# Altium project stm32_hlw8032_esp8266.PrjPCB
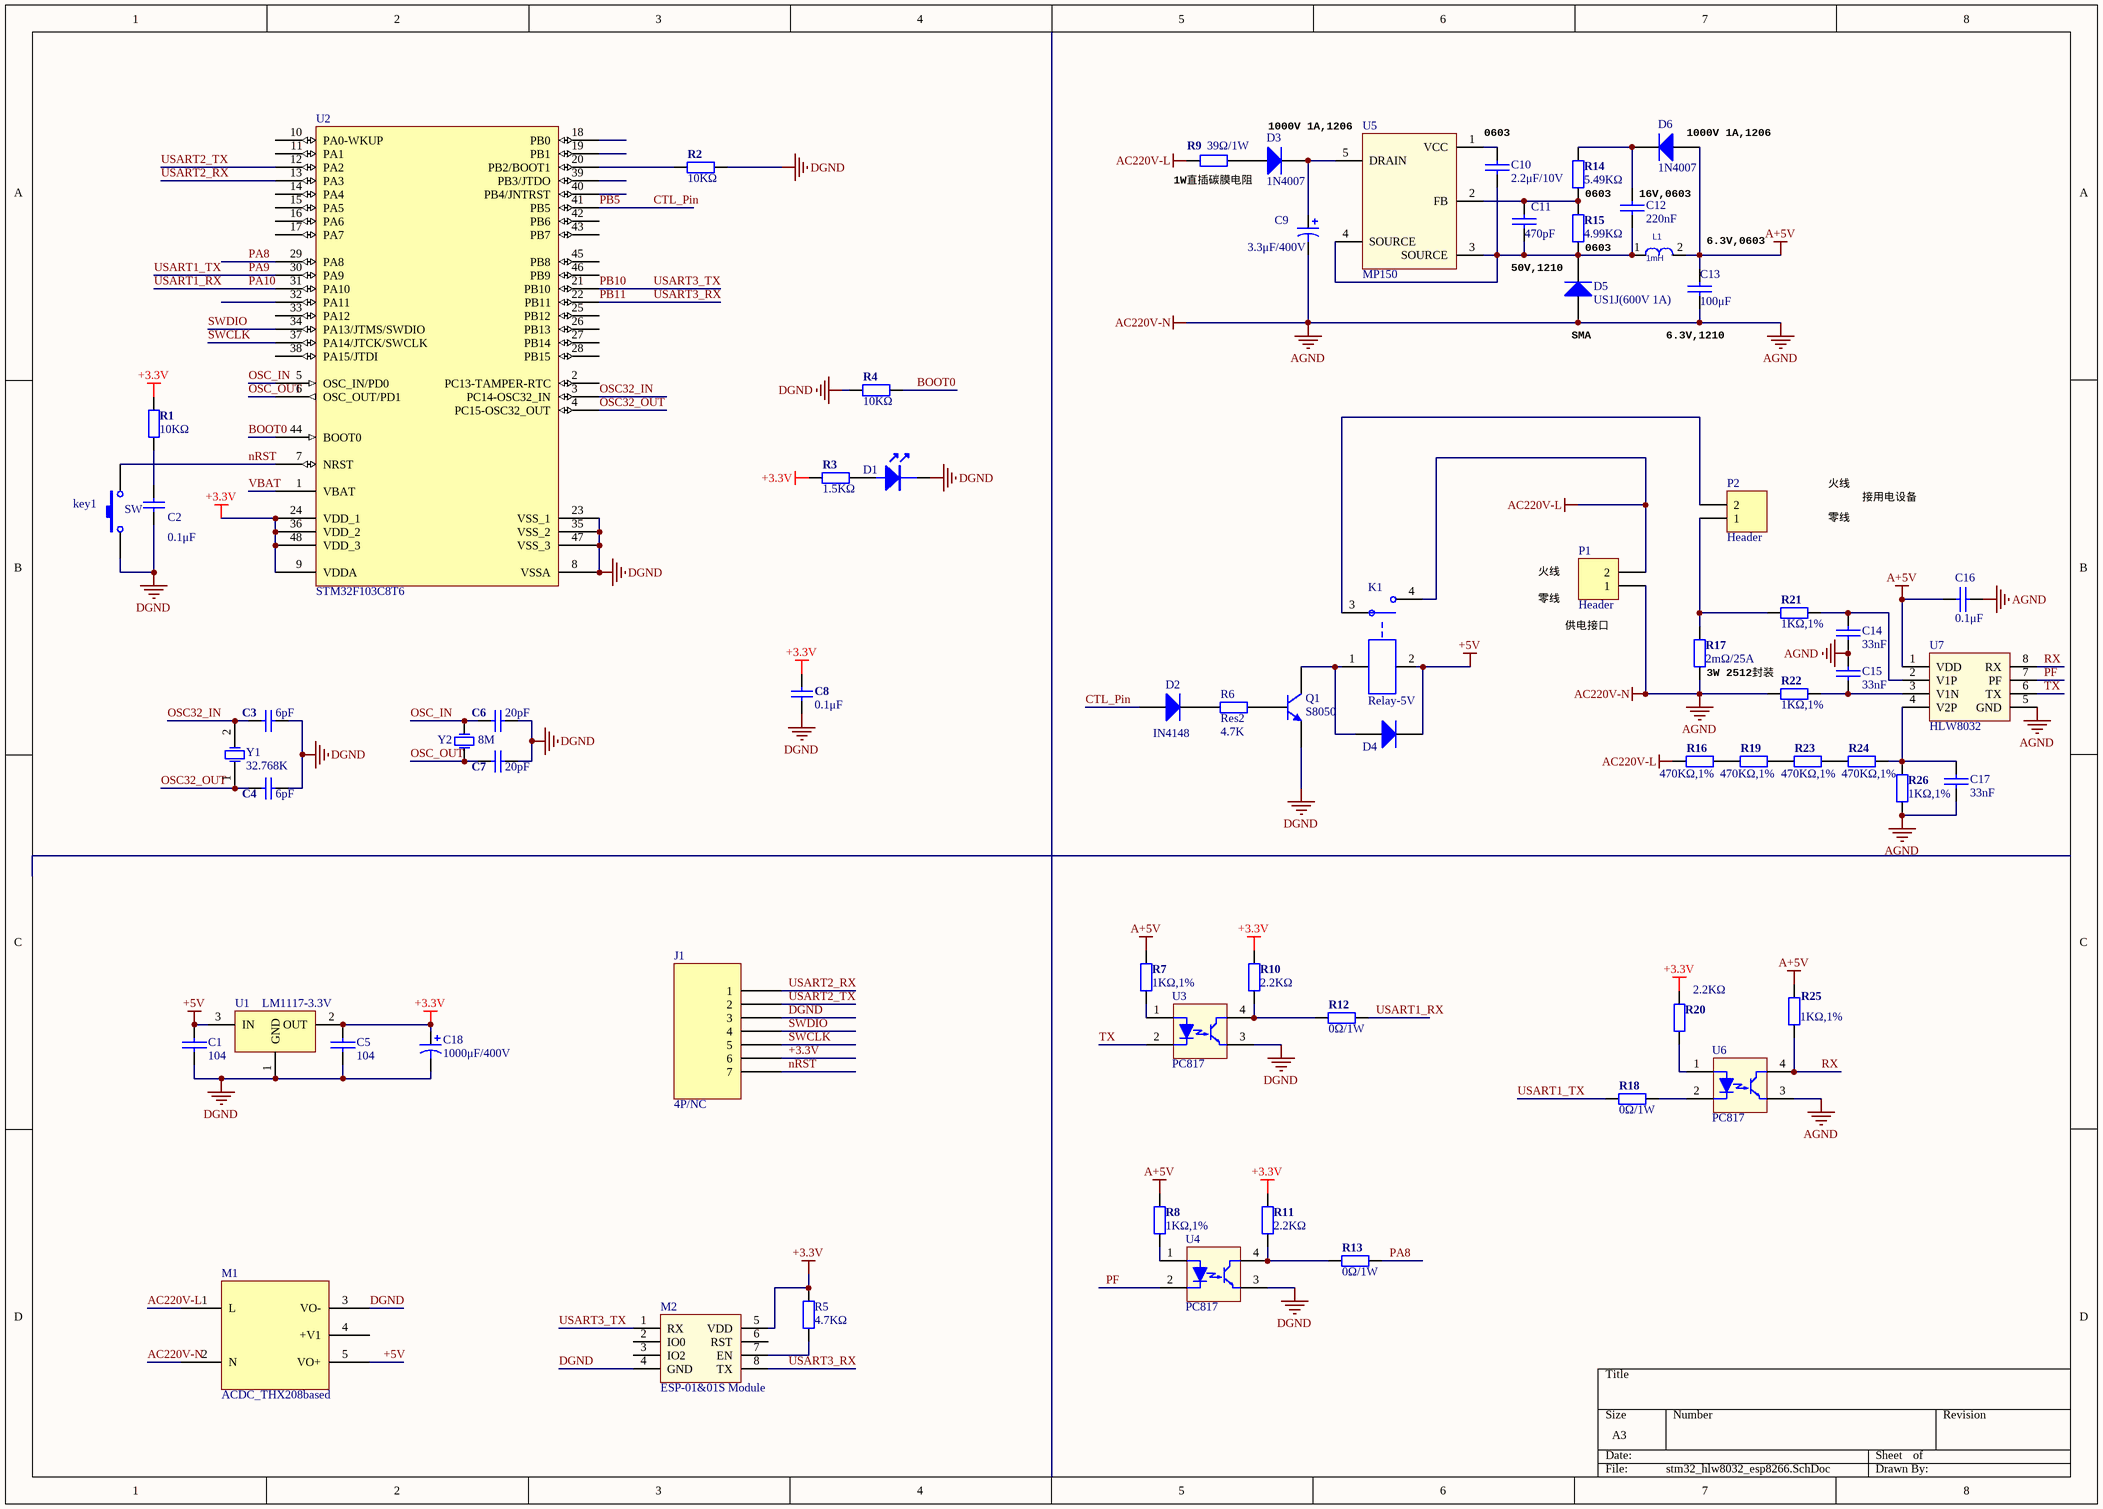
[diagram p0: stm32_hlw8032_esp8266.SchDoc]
1 sheet, 68 parts. Net scope: global (net labels, ports and power ports of the same name join across sheets).
Board file: stm32_hlw8032_esp8266.PcbDoc

## Sheet stm32_hlw8032_esp8266.SchDoc: Smartplug
size A3

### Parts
C1  104  [0603C]
C2  0.1μF  [LC-0603_C]
C3  6pF  [LC-0603_C]
C4  6pF  [LC-0603_C]
C5  104  [0603C]
C6  20pF  [LC-0603_C]
C7  20pF  [LC-0603_C]
C8  0.1μF  [LC-0603_C]
C9  3.3μF/400V  [CAP-ELECT-TH-6.3X7]
C10  2.2μF/10V  [LC-0603_C]
C11  470pF  [LC-0603_C]
C12  220nF  [LC-0603_C]
C13  100μF  [LC-1210_C]
C14  33nF  [LC-0805_C]
C15  33nF  [LC-0805_C]
C16  0.1μF  [LC-0603_C]
C17  33nF  [LC-0805_C]
C18  1000μF/400V  [CAP-ELECT-TH-6.3X7]
D1  POWER  [LC-0603_LED_S1]  (value not drawn)
D2  IN4148  [1206D]
D3  1N4007  [LC-SMA(DO-214AC)_S1]
D4  (no value)  [1206D]
D5  US1J(600V 1A)  [LC-SMA(DO-214AC)_S1]
D6  1N4007  [LC-SMA(DO-214AC)_S1]
J1  4P/NC  [HDR1X7]
K1  Relay-5V  [SJ-S-105LMH]
key1  SW  [KEY-2]
L1  1mH  [L-10X14]
M1  ACDC_THX208based  [ACDC_THX208]
M2  ESP-01&01S Module  [ESP-01&01S Module]
P1  Header  [3.81-2P]
P2  Header  [3.81-2P]
Q1  S8050  [SOT-23]
R1  10KΩ  [LC-0603_R]
R2  10KΩ  [LC-0603_R]
R3  1.5KΩ  [LC-0603_R]
R4  10KΩ  [LC-0603_R]
R5  4.7KΩ  [LC-0603_R]
R6  Res2  value 4.7K  [0603]
R7  1KΩ,1%  [LC-0805_R]
R8  1KΩ,1%  [LC-0805_R]
R9  39Ω/1W  [R-1W-THT]
R10  2.2KΩ  [LC-0603_R]
R11  2.2KΩ  [LC-0603_R]
R12  0Ω/1W  [0603]
R13  0Ω/1W  [0603]
R14  5.49KΩ  [LC-0603_R]
R15  4.99KΩ  [LC-0603_R]
R16  470KΩ,1%  [LC-0805_R]
R17  2mΩ/25A  [R2512]
R18  0Ω/1W  [0603]
R19  470KΩ,1%  [LC-0805_R]
R20  2.2KΩ  [LC-0603_R]
R21  1KΩ,1%  [LC-0805_R]
R22  1KΩ,1%  [LC-0805_R]
R23  470KΩ,1%  [LC-0805_R]
R24  470KΩ,1%  [LC-0805_R]
R25  1KΩ,1%  [LC-0805_R]
R26  1KΩ,1%  [LC-0805_R]
U1  LM1117-3.3V  [SOT-223/P2.3]
U2  STM32F103C8T6  [LC-LQFP-48_7x7x05P]
U3  PC817  [LC-SMD-4]
U4  PC817  [LC-SMD-4]
U5  MP150  [LC-SOT-23-5]
U6  PC817  [LC-SMD-4]
U7  HLW8032  [LC-SOP-8_150mil]
Y1  32.768K  [CRYSTAL]
Y2  8M  [49/U_N]

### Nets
+3.3V: C5.1 C8.2 C18.1 J1.6 M2.5(VDD) R1.2 R3.2 R5.2 R10.2 R11.2 R20.2 U1.2(OUT) U2.9(VDDA) U2.24(VDD_1) U2.36(VDD_2) U2.48(VDD_3)
+5V: C1.1 D4.2(K) K1.2 M1.5(VO+) U1.3(IN)
A+5V: C13.2 C16.1 D6.1(A) L1.2 R7.2 R8.2 R25.2 U7.1(VDD)
AC220V-L: K1.4 M1.1(L) P1.2 R9.1 R16.2
AC220V-N: C9.2 C13.1 C14.2 C15.1 C16.2 C17.2 D5.1(A) M1.2(N) P1.1 R17.2 R22.2 R26.2 U6.3(A2) U7.5(GND)  [also labelled AGND]
DGND: C1.2 C2.1 C3.2 C4.2 C5.2 C6.2 C7.2 C8.1 C18.2 D1.K J1.3 key1.1 M1.3(VO-) M2.4(GND) Q1.2(E) R2.1 R4.2 U1.1(GND) U2.8(VSSA) U2.23(VSS_1) U2.35(VSS_2) U2.47(VSS_3) U3.3(A2) U4.3(A2)
BOOT0: R4.1 U2.44(BOOT0)
CTL_Pin: D2.1(A) U2.41(PB5)  [also labelled PB5]
nRST: J1.7 key1.2 U2.7(NRST)
OSC32_IN: C3.1 U2.3(PC14-OSC32_IN) Y1.2(OSC2)
OSC32_OUT: C4.1 U2.4(PC15-OSC32_OUT) Y1.1(OSC1)
OSC_IN: C6.1 U2.5(OSC_IN/PD0) Y2.1
OSC_OUT: C7.1 U2.6(OSC_OUT/PD1) Y2.2
PA8: R13.2 U2.29(PA8)
PA9: R18.1 U2.30(PA9)  [also labelled USART1_TX]
PA10: R12.2 U2.31(PA10)  [also labelled USART1_RX]
PB10: M2.1(RX) U2.21(PB10)  [also labelled USART3_TX]
PB11: M2.8(TX) U2.22(PB11)  [also labelled USART3_RX]
PF: U4.2(K1) U7.7(PF)
RX: R25.1 U6.4(K2) U7.8(RX)
SWCLK: J1.5 U2.37(PA14/JTCK/SWCLK)
SWDIO: J1.4 U2.34(PA13/JTMS/SWDIO)
TX: U3.2(K1) U7.6(TX)
USART2_RX: J1.1 U2.13(PA3)
USART2_TX: J1.2 U2.12(PA2)
VBAT: U2.1(VBAT)
NetC2_2: C2.2 R1.1
NetC9_1: C9.1 D3.2(K) U5.5(DRAIN)
NetC10_1: C10.1 C11.1 C12.1 D5.2(K) L1.1 R15.1 U5.3(SOURCE) U5.4(SOURCE)
NetC10_2: C10.2 U5.1(VCC)
NetC11_2: C11.2 R14.1 R15.2 U5.2(FB)
NetC12_2: C12.2 D6.2(K) R14.2
NetC14_1: C14.1 R21.1 U7.2(V1P)
NetC15_2: C15.2 R22.1 U7.3(V1N)
NetC17_1: C17.1 R24.1 R26.1 U7.4(V2P)
NetD1_A: D1.A R3.1
NetD2_2: D2.2(K) R6.2
NetD3_1: D3.1(A) R9.2
NetD4_1: D4.1(A) K1.1 Q1.3(C)
NetK1_3: K1.3 P2.2
NetM2_7: M2.7(EN) R5.1
NetP2_1: P2.1 R17.1 R21.2
NetQ1_1: Q1.1(B) R6.1
NetR2_2: R2.2 U2.20(PB2/BOOT1)
NetR7_1: R7.1 U3.1(A1)
NetR8_1: R8.1 U4.1(A1)
NetR10_1: R10.1 R12.1 U3.4(K2)
NetR11_1: R11.1 R13.1 U4.4(K2)
NetR16_1: R16.1 R19.2
NetR18_2: R18.2 U6.2(K1)
NetR19_1: R19.1 R23.2
NetR20_1: R20.1 U6.1(A1)
NetR23_1: R23.1 R24.2

Not connected (* = marked no-connect by the designer): M1 4(+V1); M2 2(IO0) 3(IO2) 6(RST); U2 2(PC13-TAMPER-RTC) 10(PA0-WKUP) 11(PA1) 14(PA4) 15(PA5) 16(PA6) 17(PA7) 18(PB0) 19(PB1) 25(PB12) 26(PB13) 27(PB14) 28(PB15) 32(PA11) 33(PA12) 38(PA15/JTDI) 39(PB3/JTDO) 40(PB4/JNTRST) 42(PB6) 43(PB7) 45(PB8) 46(PB9)

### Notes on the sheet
- (near R9) 1W直插碳膜电阻
- 1000V 1A,1206
- 0603
- (near D6) 1000V 1A,1206
- (near R14) 0603
- (near C12) 16V,0603
- 6.3V,0603
- 50V,1210
- (near R15) 0603
- (near D5) SMA
- (near C13) 6.3V,1210
- 火线
- 接用电设备
- 零线
- (near P1) 供电接口
- (near R17) 3W 2512封装

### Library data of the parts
C1 C5 = CAP: Capacitor
C2-C4 C6-C8 = Cap: 贴片电容; 名称: 电容; 封装: 0805; 型号: 1μF
C9 C18 = Cap Pol1: 直插电解电容; Value: 2.2μF/400V
C10-C17 = CAP: 贴片电容; Value: 100nF (104) ±10% 50V
D1 = LED1: 发光二极管; Value: 红色
D2 D4 = Diode: Default Diode
D3 D5 D6 = Diode 1N5408: 贴片二极管
J1 = Header 7: 接口
K1 = SJ-S-105LMH: Single-Pole Dual-Throw Relay
key1 = SW: Switch
L1 = IND_8: 直插绕线电感; CISPartType: Inductor\Ferrite; OriginalSymbolOrigin: (0,0); ATHEROS KEY: 078-100LM-000; AtherosDescription: IND,SMT,SHIELDING CHOKE,10uH,7.3x7.3
M1 = ACDC: THX208Based
P1 P2 = Header 2: Header, 2-Pin
Q1 = NPN: NPN Bipolar Transistor
R1-R4 R9-R20 R23 R24 = 电阻: 贴片电阻; 型号: 1KΩ
R5 = 0805 62KΩ (6202) 1%: 贴片电阻
R6 = Res2: Resistor
R7 R8 R21 R22 R25 R26 = 电阻: 贴片电阻
U1 = 1117
U2 = STM32F103CBT6: IC; 封装: LQFP48; 厂商: ST
U3 U4 U6 = PS2501L-1-F3-A: IC
U5 = MP150: IC
U7 = HLW8032: IC
Y1 = XTAL: Crystal Oscillator
Y2 = XTAL_1: 晶振（直插）; Value: 25MHz ±20ppm 20pF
